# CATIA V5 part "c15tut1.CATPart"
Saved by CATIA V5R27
Part number: Part1
Bounding box of the stored display mesh (mm): x -21 to 122, y 0 to 45, z -43 to 1
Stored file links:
  E:\_Deepak\2017_Deepak\CATIA\Resources\Tutorial Files\Tutorials\c15_catia_v5_6r2016_tut\c15tut1.CATPart
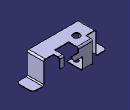
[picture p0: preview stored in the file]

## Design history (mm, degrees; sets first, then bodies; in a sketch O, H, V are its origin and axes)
SheetMetalParameters1: Thickness 1, BendRadius 2, KFactor 0.400515 {= log(min(100,max(20*SheetMetalParameters1.BendRadius,SheetMetalParameters1.Thickness)/SheetMetalParameters1.Thickness))/log(100)/2}, ReliefRadialLength 1, ReliefAxialLength 2, MinimumBendRadius 0
Body1 (main body)
  Sketch1 on xy-plane, origin (0, 0, 0), H (1, 0, 0), V (0, 1, 0)
    line L1 (0, 0) -> (101, 0)
    line L2 (101, 0) -> (101, 32)
    line L3 (101, 32) -> (82, 32)
    line L4 (82, 32) -> (82, 44)
    line L5 (82, 44) -> (74, 44)
    line L6 (74, 44) -> (74, 26)
    line L7 (74, 26) -> (47, 26)
    line L8 (47, 26) -> (47, 44)
    point P8 (47, 44)
    line L9 (47, 44) -> (20, 44)
    line L10 (20, 44) -> (20, 32)
    point P10 (20, 32)
    line L11 (20, 32) -> (0, 32)
    point P11 (0, 32)
    line L12 (0, 32) -> (0, 0)
    length L1 = 101
    length L2 = 32
    length L3 = 19
    length L5 = 8
    distance L1 L5 = 44
    distance L7 L1 = 26
    length L11 = 20
    length L9 = 27
    horizontal: L1 H, L3 H, L5 H, L7 H, L9 H, L11 H
    vertical: L2 V, L4 V, L6 V, L8 V, L10 V, L12 V
    coincidence: P8 L5, P10 L3, P11 V
  Wall1: Thickness 1, Profile Sketch1
  Flange1: Guide edge [face of Wall1 | face of Wall1], Angle 90, KFacteur 0.400515 {= log(min(100,max(20*Flange1.Radius,SheetMetalParameters1.Thickness)/SheetMetalParameters1.Thickness))/log(100)/2}, Length 44, Radius 2
  Flange2: Guide edge [face of Wall1 | face of Wall1], Angle 90, KFacteur 0.400515 {= log(min(100,max(20*Flange2.Radius,SheetMetalParameters1.Thickness)/SheetMetalParameters1.Thickness))/log(100)/2}, Length 44, Radius 2
  Flange3: Guide edge [face of Flange2 | face of Flange2], Angle 90, KFacteur 0.400515 {= log(min(100,max(20*Flange3.Radius,SheetMetalParameters1.Thickness)/SheetMetalParameters1.Thickness))/log(100)/2}, Length 22, Radius 2
  Flange4: Guide edge [face of Flange1 | face of Flange1], Angle 90, KFacteur 0.400515 {= log(min(100,max(20*Flange4.Radius,SheetMetalParameters1.Thickness)/SheetMetalParameters1.Thickness))/log(100)/2}, Length 22, Radius 2
  Sketch2 on face of Wall1, origin (47, 44, 0), H (-1, 0, 0), V (0, 0, 1)
    point P1 (0, 1)
    line L1 (0, 1) -> (0, -8)
    line L2 (0, -8) -> (-13, -8)
    line L3 (-13, -8) -> (-13, -18)
    line L4 (-13, -18) -> (8, -18)
    line L5 (8, -18) -> (8, -42)
    line L6 (8, -42) -> (27, -42)
    line L7 (27, -42) -> (27, 1)
    line L8 (27, 1) -> (0, 1)
    reference projected line E1 (27, 0) -> (27, 1) from edge [face of Wall1 | face of Wall1]
    reference projected line E2 (0, 1) -> (27, 1) from edge [face of Wall1 | face of Wall1]
    length L6 = 19
    length L7 = 43
    length L3 = 10
    distance L4 L8 = 19
    distance L3 L7 = 40
    coincidence: P1 V, L7 E1, L8 E2
    horizontal: L2 H, L4 H, L6 H
    vertical: L3 V, L5 V, L7 V, L1 V
  d_NewWallOnEdge1: NewWallOnEdge_Edge edge [face of Wall1 | face of Wall1], KFacteur 0.400515 {= log(min(100,max(20*d_NewWallOnEdge1.Radius,SheetMetalParameters1.Thickness)/SheetMetalParameters1.Thickness))/log(100)/2}, NewWallOnEdge_WallProfile Sketch2, NewWallOnEdge_Length 27, NewWallOnEdge_HeightLimitOffset 0, NewWallOnEdge_WidthOffset1 0, NewWallOnEdge_WidthOffset2 0, NewWallOnEdge_Angle 0, NewWallOnEdge_BendRadiusValue 2 {= SheetMetalParameters1.BendRadius}, NewWallOnEdge_BendTable SheetMetalParameters1
  Flange5: Guide edge [face of Wall1 | face of Wall1], Angle 90, KFacteur 0.400515 {= log(min(100,max(20*Flange5.Radius,SheetMetalParameters1.Thickness)/SheetMetalParameters1.Thickness))/log(100)/2}, Length 19, Radius 2
  Flange6: Guide edge [face of d_NewWallOnEdge1 | face of d_NewWallOnEdge1], Angle 90, KFacteur 0.400515 {= log(min(100,max(20*Flange6.Radius,SheetMetalParameters1.Thickness)/SheetMetalParameters1.Thickness))/log(100)/2}, Length 30, Radius 2
  Sketch3 on face of Wall1, origin (29.3791, 35.4737, 1), H (1, 0, 0), V (0, 1, 0)
    point P1 (-0.3791, -12.4737)
    reference projected line E1 (30.6209, 9.5263) -> (17.6209, 9.5263) from edge [face of d_NewWallOnEdge1 | face of d_NewWallOnEdge1]
    reference projected line E2 (-9.3791, 8.5263) -> (-9.3791, -3.4737) from edge [face of Wall1 | face of Wall1]
    distance P1 E1 = 22
    distance E2 P1 = 9
  Hole1: placed by Sketch3, at (29, 23, 1) direction (0, 0, -1), diameter 13, through (limit type 6)
  Sketch4 on face of Flange6, origin (31.6177, 25.4906, -41), H (1, 0, 0), V (0, 1, 0)
    point P1 (-2.6177, -2.4906)
    reference projected circle E1 centre (-2.6177, -2.4906) radius 6.5 from edge [face of Wall1 | face of Hole1]
    concentricity: P1 E1
  Hole2: placed by Sketch4, at (29, 23, -41) direction (0, 0, -1), diameter 8, through (limit type 6)
  Corner1: CornerChamferEdges (edge [face of Flange3 | face of Flange3]; edge [face of Flange3 | face of Flange3]; edge [face of Flange4 | face of Flange4]; edge [face of Flange4 | face of Flange4]), CornerRadius 7
  Corner2: CornerChamferEdges (edge [face of Wall1 | face of Wall1]; edge [face of Wall1 | face of Wall1]; edge [face of d_NewWallOnEdge1 | face of d_NewWallOnEdge1]; edge [face of Wall1 | face of Wall1]; edge [face of d_NewWallOnEdge1 | face of d_NewWallOnEdge1]; edge [face of Wall1 | face of Wall1]), CornerRadius 2
  Chamfer1: CornerChamferEdges edge [face of d_NewWallOnEdge1 | face of d_NewWallOnEdge1], ChamferAngle 45, ChamferLength1 6, ChamferLength2 0.5, ChamferPropagation 1, ChamferReverse false, ChamferType 1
